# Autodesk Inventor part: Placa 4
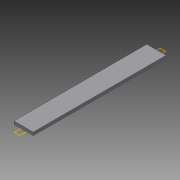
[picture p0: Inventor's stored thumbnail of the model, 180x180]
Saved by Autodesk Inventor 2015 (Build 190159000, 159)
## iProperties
Created: 2015-04
Part Number: Placa 4
Material: Generic
Document SubType Name: Modeling
Designer: suporte
Density: 1 g/cm^3
Appearance: Default
Author: suporte
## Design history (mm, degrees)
workplane "Work Plane1"
sketch "Sketch1"
  geometry: L1 (19.566, 518.599)-(0, 518.599) reference; L2 (-27.717, 0)-(-27.717, 518.599) reference; L3 (47.283, 518.599)-(47.283, 0) reference; L4 (47.283, 518.599)-(-27.717, 518.599); L5 (-27.717, 518.599)-(-27.717, 0); L6 (-27.717, 0)-(47.283, 0); L7 (47.283, 0)-(47.283, 518.599); 1 further point
  constraints: 8 end point, 2 parallel, 1 horizontal, 1 perpendicular
extrude "Extrusion1" new body sketch "Sketch1" distance "d0" = 12.5; taper "d1" = 0 deg
body "Solid1"
node "Reference1"
node "Reference2"
node "Reference3"
